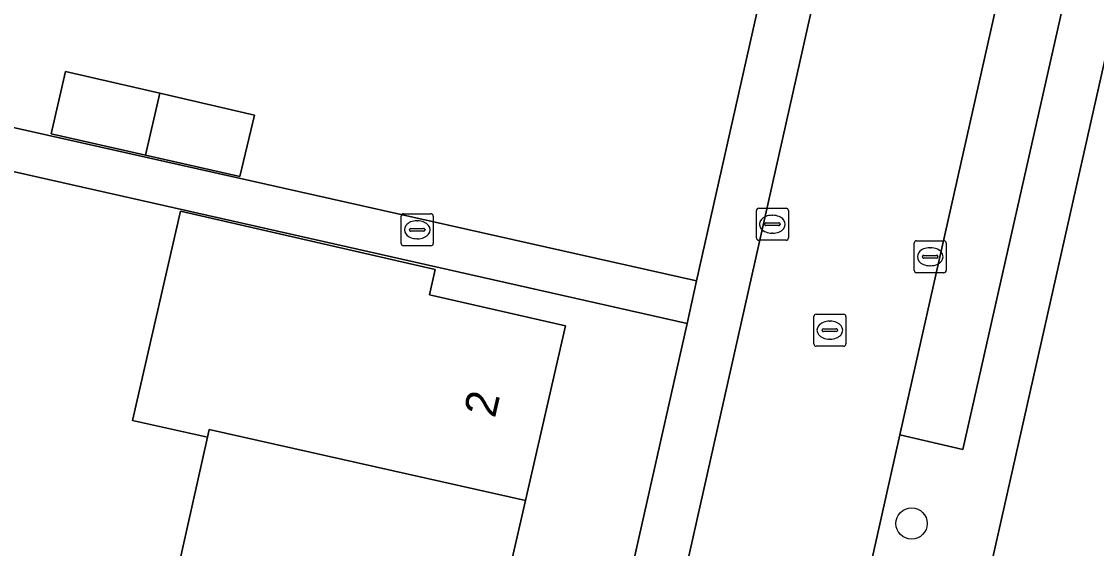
# Model space of a CAD drawing. Extents: x 161771 to 163125, y 382475 to 383179.
# Drawn here: x 162674.62 to 162708.13, y 382646.67 to 382663.1 of the extents above; entities that cross this region are included whole.
import ezdxf

# ---------------------------------------------------------------- set-up
doc = ezdxf.new("R2010")
doc.units = 0
for name, color, linetype in [('IMGEO_Boom', 7, 'Continuous'), ('IMGEO_Erf', 7, 'Continuous'), ('IMGEO_Kolk', 7, 'Continuous'), ('IMGEO_Pand', 7, 'Continuous'), ('IMGEO_Pand_nummerreeks', 7, 'Continuous'), ('IMGEO_Parkeervlak_open', 7, 'Continuous'), ('IMGEO_Rijbaan_lokaal_open', 7, 'Continuous'), ('IMGEO_Rioolput', 7, 'Continuous'), ('IMGEO_Voetpad_open', 7, 'Continuous')]:
    doc.layers.add(name, color=color, linetype=linetype)

msp = doc.modelspace()

# ---------------------------------------------------------------- linework, layer by layer
at = {"layer": 'IMGEO_Boom'}
msp.add_circle((162702.369, 382647.447), 0.489, dxfattribs=at)
at = {"layer": 'IMGEO_Erf'}
for points in [[(162654.531, 382687.464), (162649.585, 382665.364), (162695.667, 382655.016), (162699.68, 382672.847), (162700.608, 382677.107)], [(162761.303, 382667.139), (162745.71, 382670.631), (162745.534, 382669.838), (162736.11, 382671.935), (162731.157, 382649.911), (162729.877, 382650.221), (162734.809, 382672.239), (162728.181, 382673.743), (162728.356, 382674.516), (162712.056, 382678.166), (162698.037, 382615.869), (162697.672, 382614.248)], [(162682.322, 382595.727), (162687.403, 382618.3), (162695.368, 382653.689), (162673.009, 382658.73), (162666.379, 382629.265), (162665.103, 382629.55)]]:
    msp.add_lwpolyline(points, dxfattribs=at)
for points in [[(162678.936, 382660.864), (162681.881, 382660.18), (162681.422, 382658.265), (162678.487, 382658.932), (162675.543, 382659.602), (162675.99, 382661.547)], [(162679.752, 382644.443), (162679.17, 382644.573), (162680.421, 382650.136), (162678.075, 382650.663), (162679.57, 382657.185), (162687.514, 382655.364), (162687.335, 382654.58), (162691.579, 382653.607), (162690.33, 382648.165), (162689.105, 382642.826), (162689.688, 382642.693), (162688.403, 382636.923), (162687.16, 382631.345), (162685.917, 382625.767), (162684.627, 382619.975), (162681.435, 382620.69), (162680.811, 382617.902), (162677.652, 382618.597), (162678.278, 382621.384), (162672.4, 382622.706), (162673.704, 382628.507), (162674.958, 382634.084), (162676.272, 382639.929), (162678.618, 382639.402)]]:
    msp.add_lwpolyline(points, close=True, dxfattribs=at)
at = {"layer": 'IMGEO_Kolk'}
for p, q in [((162686.456, 382656.181), (162686.456, 382657.033)), ((162686.531, 382657.107), (162687.383, 382657.107)), ((162687.457, 382657.033), (162687.457, 382656.181)), ((162697.529, 382656.353), (162697.529, 382657.205)), ((162697.604, 382657.279), (162698.456, 382657.279)), ((162698.017, 382657.059), (162698.042, 382657.059)), ((162698.53, 382657.205), (162698.53, 382656.353)), ((162686.944, 382656.887), (162686.969, 382656.887)), ((162697.788, 382656.773), (162697.788, 382656.785)), ((162698.226, 382656.736), (162697.828, 382656.736)), ((162697.831, 382656.822), (162698.229, 382656.822)), ((162698.272, 382656.785), (162698.272, 382656.773)), ((162686.715, 382656.601), (162686.715, 382656.613)), ((162687.153, 382656.564), (162686.755, 382656.564)), ((162686.758, 382656.65), (162687.156, 382656.65)), ((162686.967, 382656.327), (162686.942, 382656.327)), ((162687.199, 382656.613), (162687.199, 382656.601)), ((162698.04, 382656.499), (162698.015, 382656.499)), ((162687.383, 382656.107), (162686.531, 382656.107)), ((162698.456, 382656.279), (162697.604, 382656.279)), ((162702.449, 382655.341), (162702.449, 382656.193)), ((162702.524, 382656.267), (162703.376, 382656.267)), ((162702.937, 382656.047), (162702.962, 382656.047)), ((162703.45, 382656.193), (162703.45, 382655.341)), ((162702.708, 382655.761), (162702.708, 382655.773)), ((162703.146, 382655.724), (162702.748, 382655.724)), ((162702.751, 382655.81), (162703.149, 382655.81)), ((162703.192, 382655.773), (162703.192, 382655.761)), ((162702.96, 382655.487), (162702.935, 382655.487)), ((162703.376, 382655.267), (162702.524, 382655.267))]:
    msp.add_line(p, q, dxfattribs=at)
for points in [[(162686.456, 382656.181), (162686.456, 382657.033)], [(162686.531, 382657.107), (162687.383, 382657.107)], [(162687.457, 382657.033), (162687.457, 382656.181)], [(162697.529, 382656.353), (162697.529, 382657.205)], [(162697.604, 382657.279), (162698.456, 382657.279)], [(162698.53, 382657.205), (162698.53, 382656.353)], [(162687.383, 382656.107), (162686.531, 382656.107)], [(162698.456, 382656.279), (162697.604, 382656.279)], [(162702.449, 382655.341), (162702.449, 382656.193)], [(162702.524, 382656.267), (162703.376, 382656.267)], [(162703.45, 382656.193), (162703.45, 382655.341)], [(162703.376, 382655.267), (162702.524, 382655.267)]]:
    msp.add_lwpolyline(points, dxfattribs=at)
for centre, radius, start, end in [((162686.533, 382657.031), 0.0765, 91.552, 178.448), ((162686.533, 382657.031), 0.0765, 91.552, 178.448), ((162687.381, 382657.031), 0.0765, 1.552, 88.448), ((162687.381, 382657.031), 0.0765, 1.552, 88.448), ((162697.606, 382657.203), 0.0765, 91.552, 178.448), ((162697.606, 382657.203), 0.0765, 91.552, 178.448), ((162698.454, 382657.203), 0.0765, 1.552, 88.448), ((162698.454, 382657.203), 0.0765, 1.552, 88.448), ((162697.828, 382656.782), 0.0403, 85.8775, 175.7526), ((162697.825, 382656.772), 0.0366, 178.938, 274.7102), ((162698.229, 382656.779), 0.043, 264.8664, 352.4533), ((162698.233, 382656.784), 0.0386, 1.7309, 96.639), ((162686.755, 382656.61), 0.0403, 85.8775, 175.7526), ((162686.752, 382656.6), 0.0366, 178.938, 274.7102), ((162687.156, 382656.607), 0.043, 264.8664, 352.4533), ((162687.16, 382656.612), 0.0386, 1.7309, 96.639), ((162697.606, 382656.355), 0.0765, 181.552, 268.448), ((162697.606, 382656.355), 0.0765, 181.552, 268.448), ((162698.454, 382656.355), 0.0765, 271.552, 358.448), ((162698.454, 382656.355), 0.0765, 271.552, 358.448), ((162686.533, 382656.183), 0.0765, 181.552, 268.448), ((162686.533, 382656.183), 0.0765, 181.552, 268.448), ((162687.381, 382656.183), 0.0765, 271.552, 358.448), ((162687.381, 382656.183), 0.0765, 271.552, 358.448), ((162702.526, 382656.191), 0.0765, 91.552, 178.448), ((162702.526, 382656.191), 0.0765, 91.552, 178.448), ((162703.374, 382656.191), 0.0765, 1.552, 88.448), ((162703.374, 382656.191), 0.0765, 1.552, 88.448), ((162702.748, 382655.77), 0.0403, 85.8775, 175.7526), ((162702.745, 382655.76), 0.0366, 178.938, 274.7102), ((162703.149, 382655.767), 0.043, 264.8664, 352.4533), ((162703.153, 382655.772), 0.0386, 1.7309, 96.639), ((162702.526, 382655.343), 0.0765, 181.552, 268.448), ((162702.526, 382655.343), 0.0765, 181.552, 268.448), ((162703.374, 382655.343), 0.0765, 271.552, 358.448), ((162703.374, 382655.343), 0.0765, 271.552, 358.448)]:
    msp.add_arc(centre, radius, start, end, dxfattribs=at)
for centre, major_axis, ratio, start_param, end_param in [((162698.016, 382656.779), (-0.387, 0.002), 0.722429, 4.712389, 7.853982), ((162698.041, 382656.779), (-0.39, 0.002), 0.717154, 1.570796, 4.712389), ((162686.943, 382656.607), (-0.387, 0.002), 0.722429, 4.712389, 7.853982), ((162686.968, 382656.607), (-0.39, 0.002), 0.717154, 1.570796, 4.712389), ((162702.936, 382655.767), (-0.387, 0.002), 0.722429, 4.712389, 7.853982), ((162702.961, 382655.767), (-0.39, 0.002), 0.717154, 1.570796, 4.712389)]:
    msp.add_ellipse(centre, major_axis=major_axis, ratio=ratio, start_param=start_param, end_param=end_param, dxfattribs=at)
at = {"layer": 'IMGEO_Pand'}
for points in [[(162678.936, 382660.864), (162675.99, 382661.547), (162675.543, 382659.602), (162678.487, 382658.932)], [(162681.881, 382660.18), (162678.936, 382660.864), (162678.487, 382658.932), (162681.422, 382658.265)], [(162691.579, 382653.607), (162687.335, 382654.58), (162687.514, 382655.364), (162679.57, 382657.185), (162678.075, 382650.663), (162680.421, 382650.136), (162680.47, 382650.375), (162690.33, 382648.165)], [(162690.33, 382648.165), (162680.47, 382650.375), (162680.421, 382650.136), (162679.17, 382644.573), (162679.752, 382644.443), (162679.793, 382644.631), (162689.043, 382642.555), (162689.105, 382642.826)]]:
    msp.add_lwpolyline(points, close=True, dxfattribs=at)
at = {"layer": 'IMGEO_Parkeervlak_open'}
msp.add_lwpolyline([(162707.299, 382673.793), (162702.006, 382650.214), (162703.97, 382649.758), (162709.286, 382673.345)], close=True, dxfattribs=at)
at = {"layer": 'IMGEO_Rijbaan_lokaal_open'}
for points in [[(162702.214, 382676.655), (162689.019, 382617.923), (162694.482, 382616.696), (162694.939, 382618.734), (162698.882, 382636.297), (162702.006, 382650.214)], [(162702.006, 382650.214), (162707.299, 382673.793), (162707.815, 382676.091)]]:
    msp.add_lwpolyline(points, dxfattribs=at)
at = {"layer": 'IMGEO_Rioolput'}
for p, q in [((162699.395, 382653.976), (162700.247, 382653.976)), ((162699.32, 382653.05), (162699.32, 382653.902)), ((162699.808, 382653.756), (162699.833, 382653.756)), ((162700.321, 382653.902), (162700.321, 382653.05)), ((162699.579, 382653.47), (162699.579, 382653.482)), ((162700.017, 382653.433), (162699.619, 382653.433)), ((162699.622, 382653.519), (162700.02, 382653.519)), ((162700.063, 382653.482), (162700.063, 382653.47)), ((162700.247, 382652.976), (162699.395, 382652.976)), ((162699.831, 382653.196), (162699.806, 382653.196))]:
    msp.add_line(p, q, dxfattribs=at)
for points in [[(162699.395, 382653.976), (162700.247, 382653.976)], [(162699.32, 382653.05), (162699.32, 382653.902)], [(162700.321, 382653.902), (162700.321, 382653.05)], [(162700.247, 382652.976), (162699.395, 382652.976)]]:
    msp.add_lwpolyline(points, dxfattribs=at)
for centre, radius, start, end in [((162699.397, 382653.9), 0.0765, 91.552, 178.448), ((162699.397, 382653.9), 0.0765, 91.552, 178.448), ((162700.245, 382653.9), 0.0765, 1.552, 88.448), ((162700.245, 382653.9), 0.0765, 1.552, 88.448), ((162699.619, 382653.479), 0.0403, 85.8775, 175.7526), ((162699.616, 382653.469), 0.0366, 178.938, 274.7102), ((162700.02, 382653.476), 0.043, 264.8664, 352.4533), ((162700.024, 382653.481), 0.0386, 1.7309, 96.639), ((162699.397, 382653.052), 0.0765, 181.552, 268.448), ((162699.397, 382653.052), 0.0765, 181.552, 268.448), ((162700.245, 382653.052), 0.0765, 271.552, 358.448), ((162700.245, 382653.052), 0.0765, 271.552, 358.448)]:
    msp.add_arc(centre, radius, start, end, dxfattribs=at)
for centre, major_axis, ratio, start_param, end_param in [((162699.807, 382653.476), (-0.387, 0.002), 0.722429, 4.712389, 7.853982), ((162699.832, 382653.476), (-0.39, 0.002), 0.717154, 1.570796, 4.712389)]:
    msp.add_ellipse(centre, major_axis=major_axis, ratio=ratio, start_param=start_param, end_param=end_param, dxfattribs=at)
at = {"layer": 'IMGEO_Voetpad_open'}
for points in [[(162707.815, 382676.091), (162707.299, 382673.793), (162709.286, 382673.345), (162703.97, 382649.758), (162702.006, 382650.214), (162698.882, 382636.297), (162700.827, 382635.884), (162696.914, 382618.279), (162694.939, 382618.734), (162694.482, 382616.696), (162698.037, 382615.869), (162712.056, 382678.166)], [(162700.608, 382677.107), (162699.68, 382672.847), (162695.667, 382655.016), (162695.368, 382653.689), (162687.403, 382618.3), (162689.019, 382617.923), (162702.214, 382676.655)]]:
    msp.add_lwpolyline(points, dxfattribs=at)
msp.add_lwpolyline([(162649.585, 382665.364), (162649.296, 382664.072), (162671.693, 382659.013), (162665.103, 382629.55), (162666.379, 382629.265), (162673.009, 382658.73), (162695.368, 382653.689), (162695.667, 382655.016)], close=True, dxfattribs=at)

# ---------------------------------------------------------------- texts
at = {"layer": 'IMGEO_Pand_nummerreeks'}
msp.add_text('2', height=1, rotation=77.0743, dxfattribs=at).set_placement((162689.376, 382650.712))

doc.saveas('drawing.dxf')
